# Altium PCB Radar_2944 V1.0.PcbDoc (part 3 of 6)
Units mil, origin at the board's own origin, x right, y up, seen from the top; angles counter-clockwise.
Board outline 3544.83 x 2556.65 mil, 8 copper layers (Top Layer, GND1, SIG1, PWR1, PWR2, SIG2, GND2, Bottom Layer), stack 55.2 mil thick; 301 components, 253 nets, 1055 pads, 1340 vias.
Unrouted connection lines stored in the file: 12.
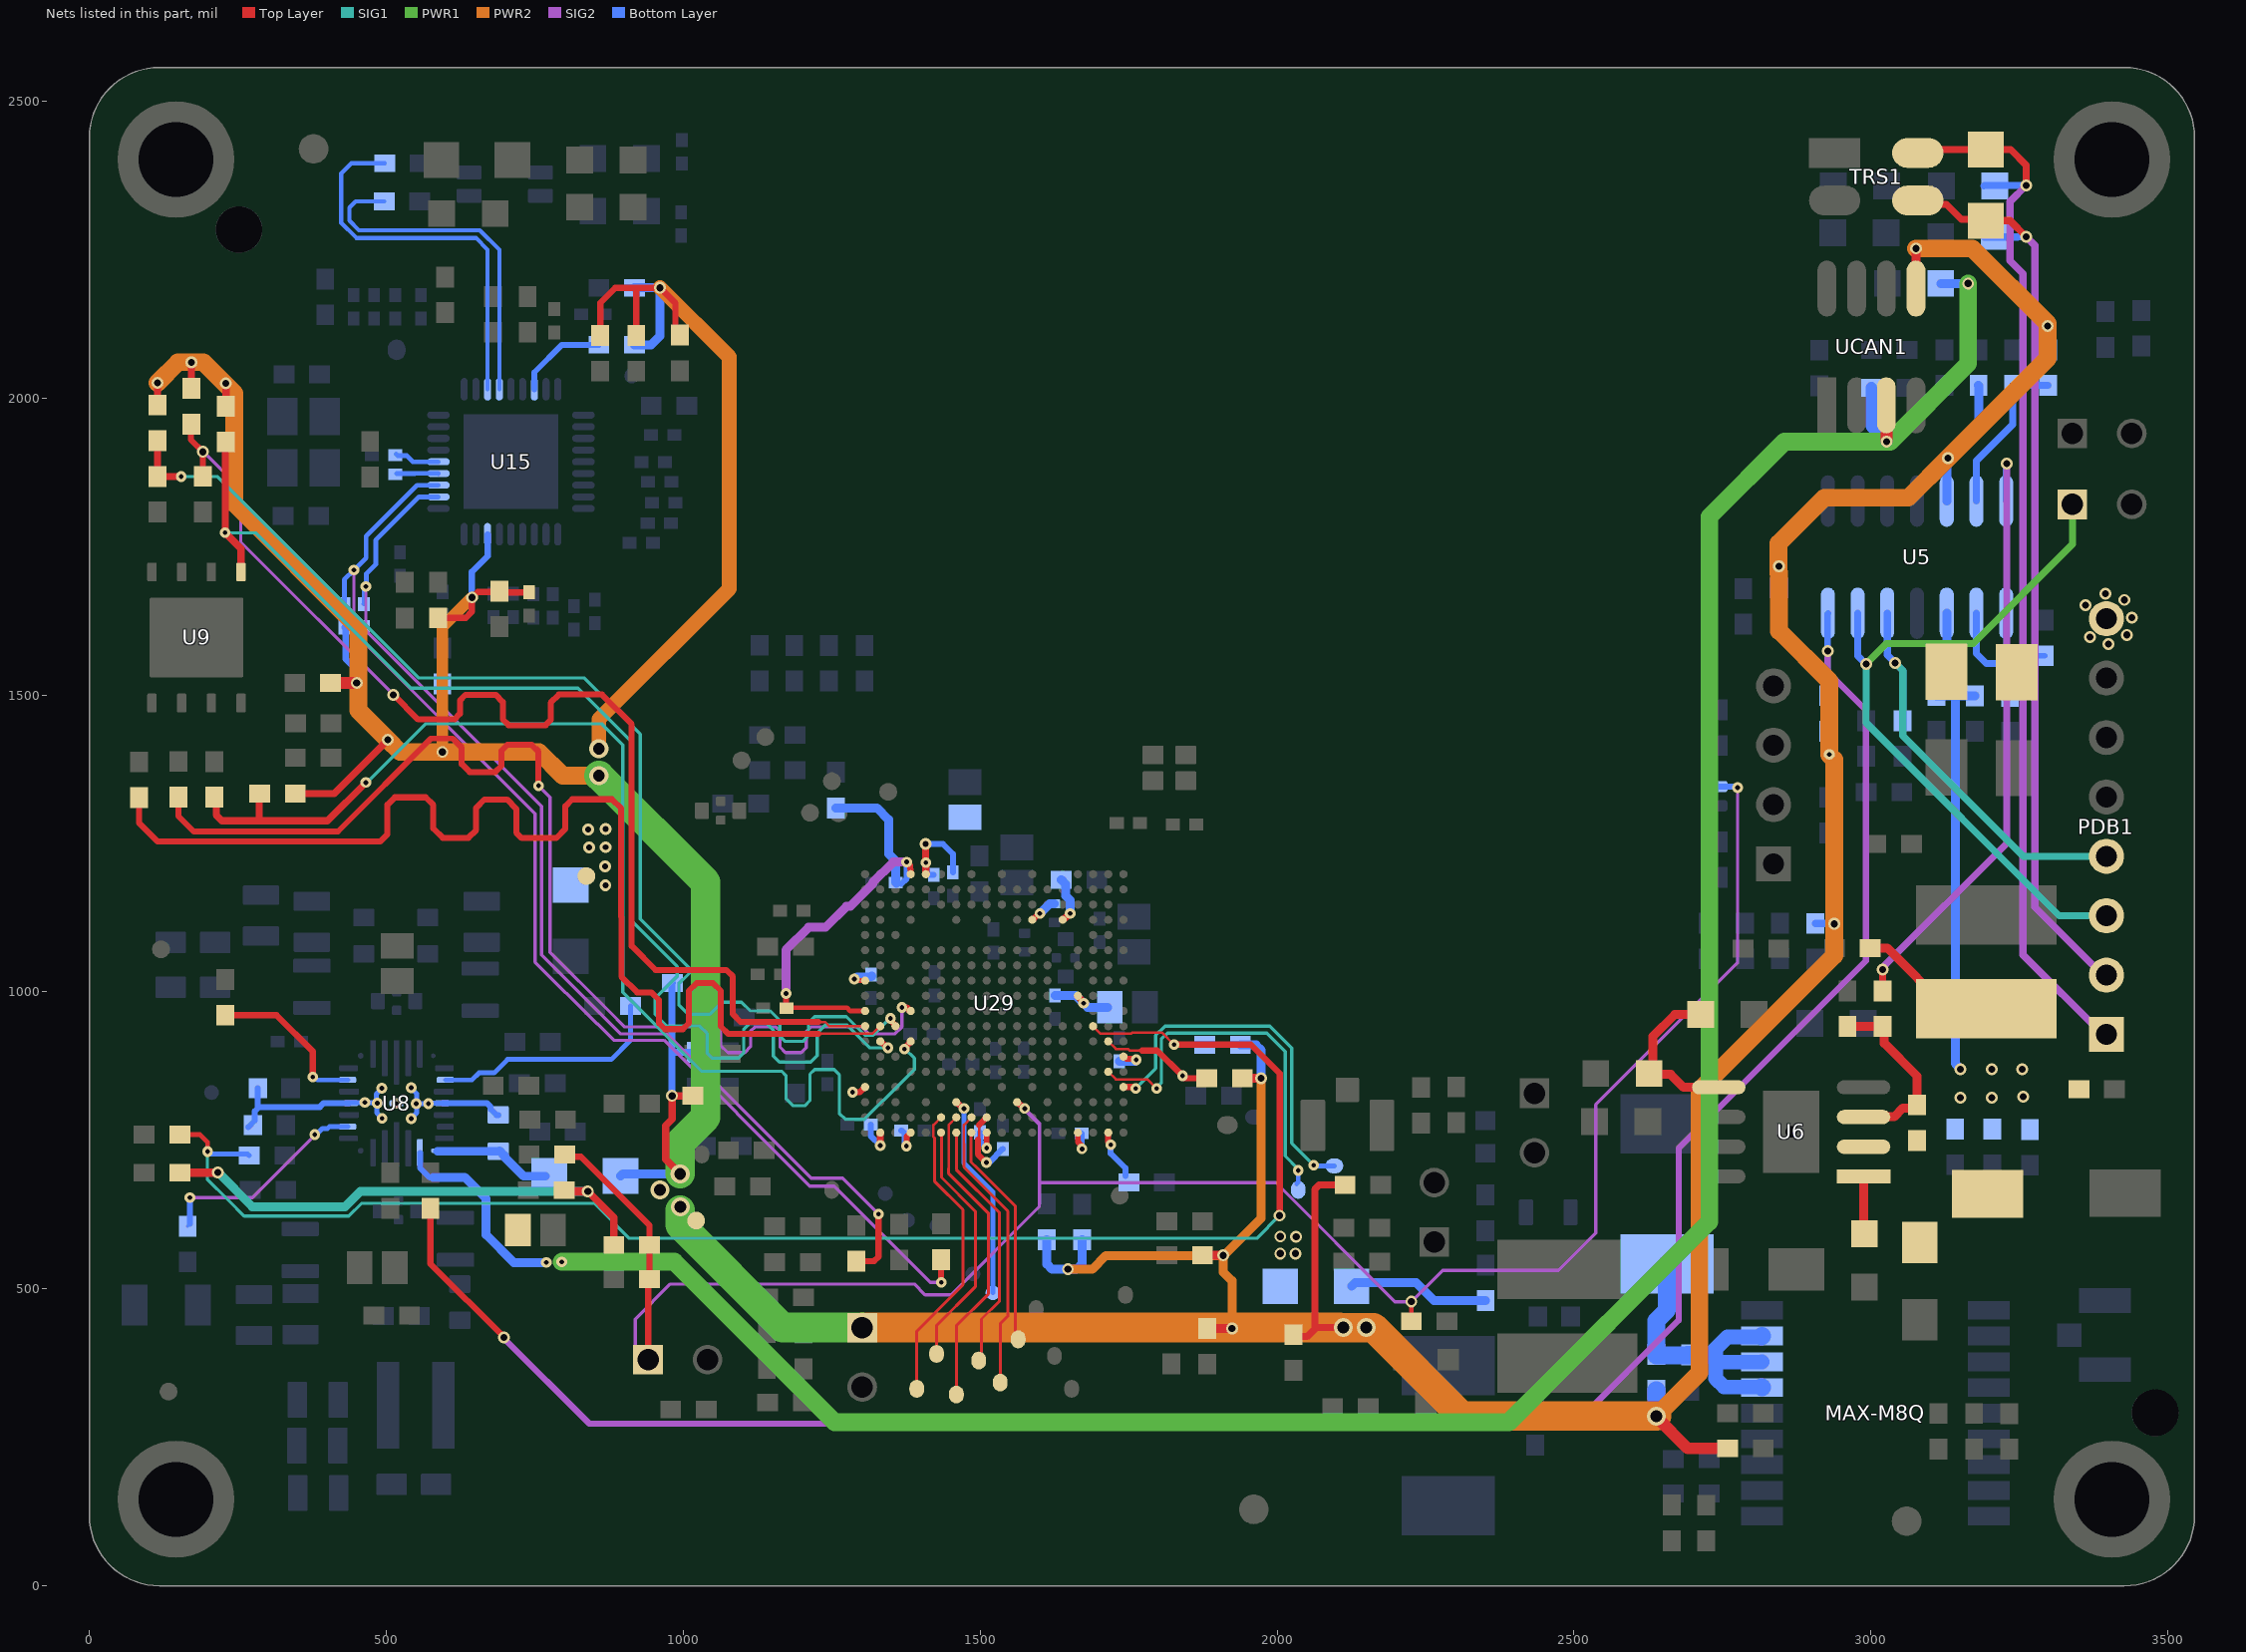
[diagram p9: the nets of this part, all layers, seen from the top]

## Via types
v1: diameter 13.77, hole 5.9, Top Layer to GND1, tented both sides, 427 vias
v2: diameter 18, hole 8, Top Layer to Bottom Layer, tented both sides, 341 vias
v3: diameter 13.77/13.77 (per signal layer), hole 5.9, Top Layer to GND1, tented both sides, 229 vias
v4: diameter 20, hole 12, Top Layer to Bottom Layer, tented both sides, 165 vias
v5: diameter 13.77, hole 5.9, Top Layer to GND1, tented top, 140 vias
v6: diameter 20, hole 10, Top Layer to Bottom Layer, tented both sides, 19 vias
v7: diameter 32, hole 20, Top Layer to Bottom Layer, tented both sides, 9 vias
v8: diameter 28, hole 16, Top Layer to Bottom Layer, tented both sides, 9 vias
v9: diameter 19.68, hole 7.87, Top Layer to Bottom Layer, tented both sides, 1 vias

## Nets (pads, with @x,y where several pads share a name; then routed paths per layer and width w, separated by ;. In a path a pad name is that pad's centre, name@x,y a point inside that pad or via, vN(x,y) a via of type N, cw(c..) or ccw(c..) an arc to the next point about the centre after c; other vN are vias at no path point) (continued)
1V4_SYNTH: C102.1 U29.G4 | length 47.8
  Top Layer w10.6: U29.G4@1587.71,1121.4 1592.73,1125.58 v2(1600.51,1132.05)
  Bottom Layer w15: v2(1600.51,1132.05) 1616.76,1148.31 C102.1@1624.94,1148.31
1V8: C5.2 C107.2 C110.1 C111.2 C112.1 C113.2 C163.2 C164.2 C165.2 C168.2 C170.2 C172.2 pad.39@836.84,1195.02 R104.2 R156.2 U29.D9 U29.D18 U29.E4 U29.K17 U29.K18 U29.P1 U29.R1 U29.U18 U29.V10 | length 1432.4
  Top Layer w4.19: 1496.12,751.72 1498.15,753.74 1498.15,768.45 ; 1498.13,768.46 1498.13,775.91
  Top Layer w8: C163.2@1173.56,973.26 1275.85,973.26 1281.25,967.86 U29.V10@1306.22,967.86
  Top Layer w10: v2(1172.94,997.35) 1172.94,977.83 C163.2@1175.42,975.34 ; v2(1376.35,1218.68) 1382.26,1212.77 1382.26,1206.87 1382.99,1206.14 U29.R1@1382.99,1198.17 ; 1496.12,751.7 1496.12,726.91 v2(1510.35,712.68) ; 1498.13,775.91 U29.K17@1510.94,788.72 ; v2(1510.94,737.09) U29.K18@1510.94,763.13 ; U29.D18@1664.49,763.13 1664.49,747.34 1669.92,741.91 1669.92,737.21 v2(1671.45,735.68)
  Top Layer w12: v2(1331.81,741.22) U29.U18@1331.81,763.13 ; v6(1408.35,1249.18) v2(1408.35,1217.68) 1408.35,1216.68 1408.58,1216.45 U29.P1@1408.58,1198.17 ; U29.E4@1638.9,1121.4 1643.92,1125.58 v2(1651.69,1132.05) ; U29.D9@1664.49,993.45 1668.48,988.3 1674.15,980.99 v2@1675.01,979.88
  SIG2 w15: v2(1172.94,997.35) 1172.94,1070.46 1211.09,1108.61 1239.42,1108.61 1274.84,1144.03 1281.06,1144.03 1318.9,1181.86 1318.9,1183.8 1353.78,1218.68 v2(1376.35,1218.68)
  Bottom Layer w10: C172.2@1316.07,776.47 1316.07,756.96 v2(1331.81,741.22) ; C5.2@1367.02,1181.56 1376.35,1190.89 v2(1376.35,1218.68) ; v2(1408.35,1217.68) 1408.35,1202.44 1414.04,1196.75 C113.2@1421.85,1196.75 ; v6(1408.35,1249.18) 1437.13,1249.18 1454.02,1232.29 C107.2@1454.02,1201.22 ; C165.2@1499.75,763.55 1499.75,748.28 v2(1510.94,737.09) ; v2(1510.35,712.68) 1515.05,712.68 C164.2@1538.03,735.65 ; v2@1670.96,736.07 C170.2@1670.96,761.82
  Bottom Layer w15: R156.2@1256.95,1309.67 1326.05,1309.67 1345.7,1290.02 1345.7,1232.37 1358.01,1220.06 C5.2@1358.01,1184.12 C5.2@1359.03,1183.1 ; C168.2@1626.1,993.77 1661.11,993.77 v2(1674.01,980.88) 1680.92,973.96 C110.1@1714.78,973.96 ; C111.2@1636.51,1188.85 1643.89,1181.47 1643.89,1161.91 1651.64,1154.17 v2@1651.64,1132.05
  other v6: 868.92,1179.67 868.57,1211.11 841.35,1243.07 868.97,1243.64 840.21,1273.54 869.12,1274.13
3.0V_GPS: CBG1.1 CGP2.2 MAX-M8Q.6 MAX-M8Q.7 MAX-M8Q.8 RG9.1 | length 567
  Bottom Layer w25: 2729.08,389 2730.46,390.39 2738.57,390.39 2740.57,376.71 2815.79,376.71 MAX-M8Q.7@2816.39,377.31 ; 2733.63,394.66 2758.05,419.08 2814.85,419.08 MAX-M8Q.8@2815.64,419.87 ; 2738.17,380.97 2738.17,349.39 2752.81,334.75 MAX-M8Q.6@2815.64,334.75
  Bottom Layer w30: CBG1.1@2656.45,541.76 CBG1.1@2656.45,541.76 2656.4,464.33 2638.45,446.38 2638.45,387.91 2695.45,387.91 CGP2.2@2695.45,388.76 ; CGP2.2@2690.84,389 2729.08,389 ; MAX-M8Q.6@2815.64,334.75 MAX-M8Q.6@2816.39,334 ; MAX-M8Q.8@2815.64,419.87 MAX-M8Q.8@2816.39,420.61
3V3: C174.2 C175.2 C176.2 C177.2 R11.1 U29.A13 U29.B18 U29.R18 U29.V8 U29.V15 | length 268.7
  Top Layer w8: v2(1288.17,1021.54) 1290.67,1019.04 U29.V8@1306.22,1019.04
  Top Layer w10: v2(1285.35,831.31) 1297.62,831.31 U29.V15@1306.22,839.9 ; v2(1375.85,740.68) 1375.85,755.99 U29.R18@1382.99,763.13 ; U29.B18@1715.67,763.13 1715.67,746.86 v2(1719.85,742.68) ; U29.A13@1741.26,891.09 1742.28,891.09 1746.2,887.16 1761.24,887.16 v2(1762.74,885.66)
  Bottom Layer w10: C177.2@1367.15,766.55 1367.99,766.55 1372.83,761.7 1372.83,745.86 1375.85,742.84 v2(1375.85,740.68) ; v2(1719.85,742.68) 1719.85,727.94 1744.57,703.22 C175.2@1744.57,689.93
  Bottom Layer w15: v2(1288.17,1021.54) 1288.98,1021.54 1292.88,1025.44 1316.61,1025.44 C174.2@1317.65,1026.48 ; C176.2@1734.35,883.25 1760.32,883.25 v2(1762.74,885.66)
  other v4: 2005.24,559.56 2031,559.56 2005.24,588.1 2032.03,587.84
3V3_VIO: C12.2 C32.1 C35.1 pad.39@1021.65,614.87 PSO1.1 R1.2 R4.1 R11.2 R18.1 R34.1 R37.1 R40.2 R43.2 R44.2 R45.2 R53.1 R106.2 R116.2 R253.2 R254.2 R255.2 R256.2 R257.2 R262.2 R263.2 R264.2 R271.2 R272.2 R273.2 R276.2 R277.2 R278.2 R279.2 R280.2 R309.2 R331.2 R333.2 R409.2 RCN25.2 RG1.2 RG9.2 Rs301.2 U5.5 U15.34 UCAN1.5 | length 12660.3
  Top Layer w10.6: R1.2@587.52,1629.69 633.61,1629.69 644.12,1640.21 v4(644.12,1664.19) 645.01,1664.19 654.03,1673.22 686.02,1673.22 C32.1@690.38,1677.59 ; C32.1@690.38,1672.59 737.85,1672.59 C35.1@740.58,1675.33 ; R257.2@860.25,2105.07 860.25,2160.28 885.39,2185.42 920.95,2185.42 ; R256.2@920.95,2105.07 920.95,2185.42 ; R255.2@986.69,2105 986.69,2159.74 v4(961.01,2185.42) 920.95,2185.42
  Top Layer w12: v4(114.62,2025.41) 114.62,1988.43 R44.2@115,1988.05 ; R40.2@172,2016 v4(172,2059.56) ; R43.2@230.06,1986.06 v4@230.06,2024.04 ; R45.2@346.96,1333.84 412.23,1333.84 v4(502.8,1424.41) ; v4(839.38,663.96) 883.25,620.09 R264.2@883.25,573.99 ; v7(994.77,693.81) 970.34,718.23 970.34,775.03 981.25,785.93 v4(981.25,824.97) 1006.52,824.97 R273.2@1008.64,827.1 ; R263.2@2027.33,419.83 2050.48,419.83 2063.31,432.66 ; v7(2111.46,434.76) 2065.41,434.76 2063.31,432.66 ; R333.2@2114.45,674.76 2070.34,674.76 2063.31,667.73 2063.31,432.66
  Top Layer w15: R262.2@152.34,695.6 215.9,695.6 v4(216.42,696.12) ; R106.2@799.35,666.13 801.52,663.96 v4(839.38,663.96) ; R309.2@1874.45,556.76 v4@1909.11,556.76 ; R331.2@1882.33,433.28 v4(1923.98,433.28) ; R272.2@1941.6,854.78 v4(1973.01,854.78) ; UCAN1.5@3075.6,2176.2 v4(3075.6,2251.61) ; UCAN1.5@3075.7,2184.31 UCAN1.5@3078.86,2187.46
  Top Layer w20: R37.1@405.98,1520.33 v4(450.19,1520.33) ; v7(2638.45,285.85) 2638.45,284.14 2691.05,231.54 RG1.2@2758.54,231.54
  PWR1 w50: v7(857.96,1364.01) 858.36,1364.01 1037.48,1184.89 1037.48,788.66 994.77,745.95 v7(994.77,693.81) ; v7@994.77,632.49 994.77,607.78 1167.46,435.09 1301.11,435.09 PSO1.1@1301.45,434.76
  PWR2 w15: v4(1647.67,532.95) 1688.66,532.95 1711.87,556.17 v4@1909.11,556.17 ; v4(1909.11,556.36) v4@1909.11,556.17 ; v4(1923.98,433.28) 1923.98,434.84 1923.98,513.6 1909.11,528.47 v4@1909.11,556.17 ; v4(1973.01,854.78) 1973.01,618.86 1913.02,558.86 1912.96,558.86 1910.27,556.17 v4@1909.11,556.17
  PWR2 w20: v4(594.45,1404.01) 594.45,1614.51 v4(644.12,1664.19)
  PWR2 w25: v7(857.96,1409.13) 857.96,1459.31 1077.29,1678.65 1077.29,2069.13 v4(961.01,2185.42)
  PWR2 w30: v4(114.62,2025.41) 149.43,2060.22 171,2060.22 191.88,2060.22 227.11,2024.98 244.29,2007.81 244.29,1821.89 453.23,1612.95 453.23,1520.33 453.23,1473.85 502.74,1424.34 523.05,1404.03 v4(594.45,1404.01) 757.16,1404.03 797.19,1364.01 v7(857.96,1364.01) ; v7(2638.45,285.85) 2711.06,358.46 2711.06,834.35 2937.86,1061.15 v4(2937.86,1114.48) 2937.86,1391.37 v2(2929.65,1399.57) ; 2844.13,1705.29 2844.13,1754.94 2921.26,1832.07 3062.85,1832.07 v4(3129.28,1898.49) 3297.24,2066.46 v4(3297.24,2120.85) 3297.24,2125.2 3170.83,2251.61 v4(3075.6,2251.61) ; 2845.27,1706.44 2845.27,1607.79 2929.65,1523.41 v2@2929.65,1402.27
  PWR2 w50: PSO1.1@1301.45,434.76 1301.53,434.84 1923.98,434.84 2105.14,434.84 2105.22,434.76 v7(2111.46,434.76) v7(2149.98,434.76) 2162.34,434.76 2311.25,285.85 v7(2638.45,285.85)
  SIG1 w15: v4(216.42,696.12) 274.27,638.27 430.41,638.27 456.09,663.96 v4(839.38,663.96)
  Bottom Layer w10.6: v4(450.19,1520.33) 450.19,1541.81 431.58,1560.43 431.58,1611.67 R4.1@429.48,1613.76 431.58,1615.86 460.11,1615.86 R34.1@462.2,1613.76 ; v4(644.12,1664.19) 644.12,1707.2 670.59,1733.66 U15.34@670.59,1770.41
  Bottom Layer w12: v4(594.45,1404.01) R280.2@594.45,1518.76 ; v4@980.8,831.42 980.8,895.83 ; R276.2@981.73,1015.17 980.8,1014.25 980.8,895.83 ; R277.2@1021.31,898.39 983.36,898.39 980.8,895.83 ; RCN25.2@2906.19,1115.14 2937.2,1115.14 v4(2937.86,1114.48)
  Bottom Layer w15: R116.2@894.45,689.94 898.31,693.81 v7(994.77,693.81) ; R254.2@917.96,2089.55 945.93,2089.55 960.56,2104.19 v4@960.56,2185.42 ; R253.2@917.96,2185.42 v4@960.56,2185.42 ; v4(961.01,2185.42) v4@960.56,2185.42 ; R278.2@1612.22,582.98 1612.22,541.74 1621.01,532.96 1662.82,532.96 1671.61,541.74 R279.2@1671.61,582.58 ; R271.2@1938.07,910.88 1964.23,910.88 1973.01,902.09 v4(1973.01,854.78) ; R11.2@2125.24,504.38 2131.7,510.85 2233.66,510.85 2264.47,480.04 R409.2@2350.98,480.04 ; Rs301.2@2845,1680 v4(2845,1716.75) ; R18.1@2928.04,1438.73 2929.65,1437.12 v2(2929.65,1399.57) ; U5.5@3127.45,1826.48 3127.45,1895.31 3129.28,1897.14 v4(3129.28,1898.49) 3129.28,1899.85 3131.78,1902.35 3131.78,1903.46 3181.46,1953.14 3181.46,2020.63 C12.2@3181.01,2021.08 ; v4(3297.24,2120.85) 3297.24,2081.95 R53.1@3298.11,2081.08
  Bottom Layer w30: v7(2638.45,285.85) RG9.2@2638.45,329.76
  other v4: 229.54,2024.56
  other v7: 995.51,637.95 960.71,666.76
3V3EN: R7.1 R8.2 R12.1 U6.3 | length 312.3
  Top Layer w15: R7.1@2960.45,941.76 R8.2@3019.45,941.76 ; U6.3@2987.58,789.38 2987.94,789.73 3039.02,789.73 3053.86,804.58 R12.1@3077.45,804.58 ; R8.2@3015.71,941.35 3022.14,934.91 3022.14,913.47 3077.45,858.17 R12.1@3077.45,809.76
3V3REG_EN: R8.1 U5.7 | length 1037.7
  Top Layer w12: R8.1@3019.45,1001.76 v4(3019.45,1037.76)
  SIG2 w12: v4(3019.45,1037.76) 3019.45,1039.93 3023.45,1043.93 3023.45,1045.07 3228.51,1250.14 v4(3228.51,1889.43)
  Bottom Layer w12: U5.7@3227.45,1826.48 3227.45,1883.17 3228.51,1884.23 v4(3228.51,1889.43)
5V0: C120.1 R16.2 RCN1.2 U8.10 UCAN1.3 | length 4594.5
  Top Layer w20: UCAN1.3@3025.7,1987.46 3026.02,1987.14 v4@3026.02,1928.39
  PWR1 w30: v2(795.58,545.31) 795.86,545.6 984.87,545.6 1255.02,275.45 2390.16,275.45 2727.93,613.23 2727.93,1800.18 2854.22,1926.47 v4(3026.39,1926.47) 3031.99,1926.47 3163.45,2057.93 v4(3163.45,2192.77)
  Bottom Layer w10: U8.10@556.9,729.17 556.9,703.57 572.78,687.69 579.47,687.69
  Bottom Layer w15: 579.47,687.69 632.16,687.69 668.11,651.74 668.11,591.1 714.75,544.46 v2@769.51,544.46 ; RCN1.2@3117.45,2192.77 v4(3163.45,2192.77)
  Bottom Layer w20: R16.2@3000.59,2017.08 3000.59,1952.27 v4(3026.39,1926.47)
  other v2: 769.51,544.63
12V_IN: C80.1 Cu1.1 Cu3.2 Cu4.1 Cu5.1 Cu7.1 L4.2 R12.2 R52.2 R332.2 TVS2.K U5.10 U6.2 | length 1082.5
  Top Layer w15: R332.2@2998.45,1073.76 3027.17,1073.76 3129.17,971.75 L4.2@3193.99,971.75
  Bottom Layer w15: U5.10@3127.45,1637.51 3127.45,1553.13 3110.04,1535.73 C80.1@3110.04,1498.73 3144.17,1498.73 ; v4(3150.42,869.67) 3150.42,871.03 3141.72,879.73 3141.72,1496.28 3144.17,1498.73 ; R52.2@3175.02,1498.57 3174.86,1498.73 3144.17,1498.73
  other v4: 3150.42,821.83 3203.14,821.83 3256.07,823.34 3203.14,869.67 3254.65,869.67
+3.3VD: C124.2 R116.1 U8.9 | length 198.1
  Bottom Layer w15: 586.11,731.73 C124.2@688.49,731.73 ; C124.2@690.75,732.43 698.71,724.47 698.71,722.57 731.61,689.67 R116.1@767.62,689.67
AGND: C3.1 C123.1 C124.1 NT1.2 NT2.1 NT3.1 NT4.1 U8.5 U8.19 | length 550
  Bottom Layer w8.3: U8.19@437.46,812.84 438.15,813.53 463.53,813.53 v2(463.73,813.74) 464.23,813.24 v2@484.23,813.24 ; v2@485.31,813.33 v2(484.73,812.74) ; v2(492.33,837.74) 492.33,837.18 483.17,828.03 483.17,814.29 v2@484.23,813.24 ; v2(492.93,786.94) 492.93,787.51 483.79,796.65 483.79,811.8 v2(484.73,812.74) ; v2(541.93,786.74) 541.93,787.14 551.24,796.45 551.24,811.03 v2@550.5,811.77 ; v2(541.93,838.54) 541.93,837.93 551.02,828.83 551.02,812.64 v2(550.33,811.94) ; v2@548.94,813.33 v2(550.33,811.94) ; U8.5@594.3,812.34 571.54,812.34 v2(570.97,811.77) v2@550.5,811.77 ; v2@484.23,813.24 v2(484.73,812.74) ; v2(550.33,811.94) v2@550.5,811.77
  Bottom Layer w10: C123.1@267.7,772.46 278.44,783.21 278.44,798.92 285.81,806.29 ; 283.7,804.18 C3.1@283.7,838.07 ; 283.7,806.29 388.12,806.29 394.67,812.84 U8.19@437.46,812.84 ; U8.5@594.3,812.34 669.92,812.34 675.78,806.48 675.78,802.52 685.54,792.76 C124.1@688.49,792.76
  other v2: 517.29,812.08
AR_NERROUT: DS2.2 R76.1 R271.1 U29.C11 | length 2694.9
  Top Layer w4.19: U29.C11@1690.08,942.27 1702.87,929.47 1746.56,929.47 1753.93,929.49 1756.22,931.77 1806,931.77 v2(1826.57,911.2)
  Top Layer w8.3: DS2.2@152.34,759.66 186.36,759.66 199.11,746.91 v2(199.11,731.09)
  Top Layer w10.6: v2(1826.57,911.2) 1955.85,911.2 2004.51,862.54 2004.51,624.08 v4(2003.85,623.43)
  SIG1 w5.5: v2(199.11,731.09) 198.67,730.65 198.67,684.59 233.94,649.32 260.74,622.52 436.93,622.52 458.37,643.96 850.44,643.96 909.23,585.16 1965.59,585.16 v4(2003.85,623.43) ; v2(1826.57,911.2) v2@1827.99,909.78
  Bottom Layer w8.3: v2(199.11,731.09) 203.39,726.81 266.82,726.81 R76.1@269.09,724.53 ; v2(1826.57,911.2) 1826.89,910.88 R271.1@1863.39,910.88
AR_NRST: C105.2 D4.2 J11.1 R99.1 R264.1 R266.1 U29.H16 | length 3475.7
  Top Layer w8: R266.1@2225.96,445.59 v4(2225.96,478.37)
  Top Layer w10.6: R99.1@800.58,726.29 804.44,722.43 827.78,722.43 943.25,606.95 R264.1@943.25,573.99 C105.2@943.25,516.71 940.82,514.27 J11.1@940.82,380.84 ; U29.H16@1562.12,814.31 1567.14,810.13 v2(1574.92,803.66)
  SIG2 w5.5: J11.1@919.16,376.14 919.16,448.96 978.26,508.06 1389.28,508.06 1407.22,490.12 1451.33,490.12 1599.46,638.25 1599.46,643 ; 1598.4,777.41 1574.92,800.9 v2(1574.92,803.66) 1599.79,778.79 1599.79,678.71 ; 1599.79,643 1599.79,678.71 ; v2(2775.15,1344.1) 2775.15,1048.9 2536.54,810.3 2536.54,593.94 2473.59,530.99 2278.58,530.99 v4(2225.96,478.37) 2198.44,478.37 1998.1,678.71 1599.79,678.71
  Bottom Layer w10: D4.2@2743.49,1345.86 2771.22,1345.86 2772.98,1344.1 v2(2775.15,1344.1)
AR_QSPI_CLK: R47.2 U29.R10 | length 1973.6
  Top Layer w10: R47.2@149.79,1327.6 149.79,1296.19 175.87,1270.11 418.65,1270.11 575.14,1426.59 611.79,1426.59 627.05,1411.32 627.05,1383.64 640.42,1370.27 683.44,1370.27 694.12,1380.95 694.12,1406.38 703.59,1415.85 745.11,1415.85 756.32,1404.64 v2(756.32,1347.09)
  Top Layer w10.6: v2@1368.19,973.79 1376.19,973.79 1382.13,967.86 U29.R10@1382.99,967.86
  SIG2 w5.5: v2(756.32,1347.09) 775.88,1327.53 775.88,1066.63 874.31,968.21 901.56,940.95 1054.9,940.95 1063.02,932.83 1063.02,909.69 1074.91,897.8 1103.63,897.8 1113.38,907.55 1113.38,933.81 1120.51,940.95 1156.06,940.95 1163.06,933.94 1163.06,906.87 1172.13,897.8 1198.4,897.8 1206.91,906.32 1206.91,932.83 1215.04,940.95 1227.35,940.95 1300.78,940.95 1312.25,929.47 1356.75,929.47 1368.19,940.91 v2@1368.19,973.97
  other v2: 1368.11,973.97
AR_QSPI_CS: R43.1 U9.1 U29.U12 | length 2181.2
  Top Layer w10.6: U29.U12@1331.81,916.68 1336.83,912.5 v2(1344.6,906.02)
  Top Layer w12: R43.1@228.98,1918.49 228.98,1773.74 v2(228.51,1773.28) 255.44,1746.35 U9.1@255.44,1706.9
  SIG1 w5.5: v2(228.51,1773.28) 229.12,1772.68 280.55,1772.68 541.78,1511.45 823.1,1511.45 912.73,1421.82 912.73,1119.95 989.95,1042.74 989.95,1026.44 952.71,989.21 952.71,962.18 972.21,942.68 1027.81,942.68 1040.16,930.33 1040.16,896.96 1048.52,888.6 1092.9,888.6 1101.63,897.33 1101.63,936.71 1111.42,946.5 1140.42,946.5 1151.63,935.3 1151.63,892.21 1162.1,881.74 1214.53,881.74 1225.39,892.6 1225.39,930.36 1239.1,944.06 1275.74,944.06 1313.78,906.02 v2(1344.6,906.02)
AR_QSPI_D0: R61.2 U29.U11 | length 2052.8
  Top Layer w4.19: 1227.35,929.47 1318.05,929.47 1330.84,942.27 U29.U11@1331.81,942.27
  Top Layer w10.2: R61.2@83.55,1327.6 83.55,1284.59 115.14,1253.01 489.82,1253.01 502.01,1265.2 502.01,1315.06 514.56,1327.6 566.33,1327.6 579.12,1314.81 579.12,1275.11 595,1259.24 638.16,1259.24 651.17,1272.25 651.17,1309.71 665.36,1323.9 703.29,1323.9 719,1308.2 719,1268.29 728.18,1259.11 786.22,1259.11 801.52,1274.4 801.52,1312.72 813.07,1324.27 880.04,1324.27 895.43,1308.87 895.43,1126.27 895.95,1125.75 895.95,1025.66 922.51,999.11 946.39,999.11 959.12,986.38 959.12,947.26 969.14,937.25 999.31,937.25 1009.44,947.38 1009.44,1001.66 1022.61,1014.82 1049.98,1014.82 1063.13,1001.67 1063.13,941.96 1075.62,929.47 1227.35,929.47
AR_QSPI_D1: R40.1 R46.1 U29.V11 | length 2042.5
  Top Layer w4.19: 1227.35,949.27 1239.07,949.27 1246.07,942.27 U29.V11@1306.22,942.27
  Top Layer w10.2: R40.1@171,1955.85 171,1929.55 v4(191.25,1909.3) 191.25,1868.1 R46.1@191.37,1867.99 ; v4(511.8,1500.15) 512.19,1500.15 553.51,1458.83 614.51,1458.83 623.92,1468.24 623.92,1490.64 633.43,1500.15 684.17,1500.15 696.13,1488.19 696.13,1458.88 705.83,1449.18 768.1,1449.18 776.73,1457.8 776.73,1486.73 790.69,1500.69 863.05,1500.69 913.15,1450.59 913.15,1077.13 953.53,1036.75 1072.68,1036.75 1083.41,1026.02 1083.41,962.62 1096.75,949.27 1227.35,949.27
  SIG2 w5.5: v4@193.06,1908.73 255.07,1846.72 255.07,1756.88 v4(511.8,1500.15)
AR_QSPI_D2: R44.1 R48.1 U29.T11 | length 2031.8
  Top Layer w10: v2@1349.48,955.74 1349.48,951.05 U29.T11@1357.4,943.13
  Top Layer w10.6: U29.T11@1357.4,942.27 U29.T11@1357.4,943.13
  Top Layer w12: R44.1@114.62,1928.43 R44.1@115,1928.05 114.8,1927.85 R48.1@114.8,1867.8 v2(154.5,1867.8)
  SIG1 w5.5: v2@156.17,1867.8 215.1,1867.8 554.15,1528.74 832.8,1528.74 927.67,1433.87 927.67,1122.88 1009.92,1040.62 1009.92,1030.86 992.55,1013.5 992.55,978.5 1008.58,962.47 1044.81,962.47 1064.97,982.64 1098.13,982.64 1112.81,967.95 1146.7,967.95 1162.68,951.98 1162.68,925.91 1171.91,916.68 1201.1,916.68 1210.9,926.48 1210.9,947.98 1221.35,958.43 1227.35,958.43 1274.67,958.43 1305.75,927.35 1319.69,927.35 v2@1347.38,955.03
  other v2: 1349.07,955.23
AR_QSPI_D3: R45.1 R49.2 U29.R12 | length 2077.6
  Top Layer w10.6: v2(1372.34,903.88) 1378.81,911.66 U29.R12@1382.99,916.68
  Top Layer w12: R49.2@213.52,1327.6 213.52,1297.55 222.96,1288.11 286.09,1288.11 ; R45.1@286.96,1333.84 286.09,1332.97 286.09,1288.11 ; v2(465.42,1352.54) 400.98,1288.11 286.09,1288.11
  SIG1 w5.5: v2@463.64,1348.66 566.4,1451.42 862.39,1451.42 898.26,1415.55 898.26,999.04 1030.91,866.39 1166.13,866.39 1172.94,859.58 1172.94,820.67 1185.28,808.33 1204.63,808.33 1213.38,817.08 1213.38,861.44 1221.32,869.38 1253.98,869.38 1262.74,860.61 1262.74,795.64 1273.21,785.17 1304.81,785.17 1367.99,848.36 1389.06,869.42 1389.06,888.25 1373.42,903.88 v2(1372.34,903.88)
AR_WRMRST: R272.1 U29.B12 | length 180.5
  Top Layer w4.19: U29.B12@1715.67,916.68 1728.46,903.88 1749.28,903.88 1751.58,901.58 1768.72,901.58 1768.97,901.83 1772.45,901.83 1772.98,901.3
  Top Layer w10.6: 1772.98,901.3 1798.14,901.3 1838.58,860.86 v2@1842.67,856.78 ; v2(1840.88,858.96) 1845.06,854.78 R272.1@1866.92,854.78 ; R272.1@1881.09,854.27 R272.1@1881.6,854.78
BOOT: C1.1 U6.1 | length 97
  Top Layer w15: U6.1@2987.58,689.38 2987.58,594.42 C1.1@2989,593
BSS_UARTA_TX: pad.6 U29.M16 | length 347.3
  Top Layer w10.6: U29.M16@1459.76,814.31 1464.78,810.13 v2(1472.56,803.66)
  Bottom Layer w8.3: v2(1472.56,803.66) 1472.56,711.98 1521.54,662.99 pad.6@1521.54,493.3
CAN1H: PDB1.3 PL1.1 U5.13 | length 1227.9
  PWR1 w12: v4(2991.56,1552.27) 3025.76,1586.47 3172.04,1586.47 3339.05,1753.49 PL1.1@3339.05,1820.83
  SIG1 w12: v4(2991.56,1552.27) 2991.56,1453.31 3316.59,1128.28 PDB1.3@3396.36,1128.28
  Bottom Layer w12: U5.13@2977.45,1637.51 2977.45,1565.91 2991.08,1552.27 v4(2991.56,1552.27)
CAN1L: PDB1.4 R24.1 U5.12 | length 747
  SIG1 w12: v4(3040.67,1553.84) 3053.49,1541.02 3053.49,1431.45 3256.66,1228.28 PDB1.4@3396.36,1228.28
  Bottom Layer w12: U5.12@3027.45,1637.51 3027.45,1567.06 3053.89,1540.62 3053.89,1457.49 R24.1@3052.99,1456.59
CAN2H: PDB1.1 RCN4.1 RCN5.1 TRS1.4 | length 1806.4
  Top Layer w12: TRS1.4@3078.86,2412.57 3084.32,2418.02 3235.29,2418.02 3261.41,2391.91 v4(3261.41,2358.02)
  SIG2 w12: v4(3261.41,2358.02) 3234,2330.62 3234,2231.02 3255.74,2209.28 3255.74,1062.46 PDB1.1@3389.45,928.76
  Bottom Layer w12: RCN5.1@3189.89,2357.04 3190.88,2358.02 v4(3261.41,2358.02)
CAN2L: PDB1.2 RCN2.1 RCN4.2 TRS1.3 | length 1580.9
  Top Layer w12: TRS1.3@3058.88,2332.57 3065.69,2325.76 3127.17,2325.76 3152.18,2300.75 3171.25,2300.75 RCN4.2@3177,2295 ; RCN4.2@3193.15,2298.02 3193.77,2298.64 3233.92,2298.64 v4(3261.41,2271.15)
  SIG2 w12: v4(3261.41,2271.15) 3275.93,2256.62 3275.93,1142.27 PDB1.2@3389.45,1028.76
  Bottom Layer w12: RCN2.1@3189.89,2271.78 3190.7,2270.97 3246.87,2270.97 3247.05,2271.15 v4(3261.41,2271.15)
CAN_EN: R53.2 R54.2 U5.6 | length 279.2
  Bottom Layer w12: U5.6@3177.45,1826.48 3177.45,1894.04 3238.73,1955.32 3238.73,2020.89 R54.2@3238.92,2021.08 R53.2@3298.11,2021.08
CAN_nFAULT: R233.2 U5.8 | length 130
  Bottom Layer w10: U5.8@3227.45,1637.51 3227.45,1577.37 3238.92,1565.91 R233.2@3292.55,1565.91
CAN_WAKE: R55.1 U5.9 | length 176.3
  Bottom Layer w12: U5.9@3177.45,1637.51 3177.45,1569.69 3194,1553.13 3215.36,1553.13 3234.35,1534.14 3234.35,1497.81 R55.1@3233.95,1497.41
CANB_NSTB: R17.1 R18.2 U5.14 | length 3796.5
  Top Layer w10.6: R17.1@574.32,635.6 574.32,542.28 v4(698.2,418.4)
  SIG2 w10.6: v4@697.86,417.02 841.9,272.98 2502.26,272.98 2676.13,446.85 2676.13,736.67 2991.56,1052.1 2991.56,1474.57 2926.96,1539.17 v4@2926.96,1567.77
  Bottom Layer w10.6: U5.14@2927.45,1637.51 2926.59,1636.65 2926.59,1500.18 R18.2@2928.04,1498.73
  other v4: 2926.96,1573.82
CSI2_RX0_0_N: pad.32 U29.N18 | length 412.5
  Top Layer w5: pad.32@1426.64,401.16 1426.64,438.43 1491.67,503.45 1491.67,630.65 1434.84,687.48 1434.84,702.68 1434.83,754.26 ccw(c1422.84,754.26) 1434.34,757.68 1434.2,758.14 U29.N18@1434.17,763.13
CSI2_RX0_0_P: pad.21@1393.26,331.76 U29.N17 | length 524.5
  Top Layer w4: 1421.38,755.72 1421.38,775.93 U29.N17@1434.17,788.72
  Top Layer w5: pad.21@1393.26,322.16 1393.26,429.3 1470.9,506.94 1470.9,633.46 1422.84,681.53 1422.84,754.26 1421.38,755.72
CSI2_RX0_1_N: pad.21@1497.54,379.3 U29.M18 | length 426.3
  Top Layer w5: U29.M18@1459.88,763.01 1459.88,700.73 1532.6,628.02 1532.6,479.61 1502.18,449.19 1502.18,394.72 1501.36,393.91 1501.36,380.93 pad.21@1502.18,380.11
CSI2_RX0_1_P: pad.33 U29.M17 | length 522.2
  Top Layer w4: 1446.97,702.68 1446.97,775.93 U29.M17@1459.76,788.72
  Top Layer w5: 1446.97,702.68 1446.97,694.04 1514.23,626.78 1514.23,491.81 1459.88,437.46 pad.33@1459.88,322.16
CSI2_RX0_CLK_N: pad.19 U29.L18 | length 381.3
  Top Layer w5: U29.L18@1485.35,763.13 1484.55,762.33 1484.55,713.85 1495.72,702.68 1558.78,639.61 1558.78,430.47 1559.13,430.13 1559.13,419.83 pad.19@1563.91,415.04
CSI2_RX0_CLK_P: pad.20 U29.L17 | length 488
  Top Layer w4: 1472.56,744.57 1472.56,775.93 U29.L17@1485.35,788.72
  Top Layer w5: 1472.56,744.57 1472.56,705.03 1546.78,630.8 1546.78,454.04 1533.63,440.89 pad.20@1533.63,342.26
DSS_UARTA_RX: pad.36 U29.B14 | length 638
  Top Layer w4.19: U29.B14@1715.67,865.5 1728.46,852.7 1749.26,852.7 ; 1749.28,852.69 1781.72,852.69 v2(1797,837.4)
  SIG1 w5.5: v2(1797,837.4) 1797,838.89 1804.99,846.88 1804.99,920.29 1815.25,930.55 1982.87,930.55 2013.54,899.88 2013.54,723.7 2035.53,701.7 v2(2035.53,699.21)
  Bottom Layer w8: pad.36@2032.88,676.77 2035.53,679.42 v2(2035.53,699.21)
DSS_UARTA_TX: pad.35 U29.A15 | length 623.3
  Top Layer w10.6: U29.A15@1741.26,839.9 1759.23,839.9 v2(1761.73,837.4)
  SIG1 w5.5: v2(1761.73,837.4) 1795.59,871.26 1795.59,926.88 1811.07,942.36 1987.76,942.36 2024.54,905.58 2024.54,745.38 v2(2061.68,708.24)
  Bottom Layer w8: v2(2061.68,708.24) 2062.79,707.13 pad.35@2096.22,707.13
ET_12V: Dr8.A Dr9.A PDB1.8
  other v4: 3399.61,1585.78 3368.46,1597.34 3430.76,1601.1 3439.05,1630.25 3361.17,1651.35 3426.74,1659.89 3394.84,1670.44
ETH2_CLKOUT: R254.1 U15.16 | length 156.3
  Bottom Layer w10: U15.16@749.33,2014.6 749.33,2043.04 795.84,2089.55 R254.1@857.96,2089.55
ETH2_INT: R22.1 R34.2 U15.2 | length 1851.7
  Top Layer w10.6: R22.1@1291.45,546.76 1321.49,546.76 1328.77,554.04 v2(1328.77,626.12)
  SIG2 w5.5: v2(465.42,1682.53) 465.42,1608.37 761.55,1312.24 761.55,1062.06 894.13,929.47 972.17,929.47 1215.26,686.38 1268.51,686.38 v2(1328.77,626.12)
  Bottom Layer w8: R34.2@462.2,1653.13 463.05,1653.99 463.05,1679.67 v2@463.5,1680.12 ; v2(465.42,1682.53) 466.63,1683.74 466.63,1704.08 482.36,1719.8 482.36,1760.7 555.11,1833.45 U15.2@587.86,1833.45
ETH2_NRST: R4.2 R23.1 U15.3 | length 2030.1
  Top Layer w10.6: v2(1434.73,510.85) 1434.1,511.48 R23.1@1434.1,549.42 R23.1@1441.52,542.01
  SIG2 w5.5: v2(445.47,1710.23) 445.47,1605.28 750.55,1300.2 750.55,1050.1 854.44,946.21 855.35,946.21 883.08,918.47 967.61,918.47 1212.99,673.09 1253.77,673.09 1416.02,510.85 v2(1434.73,510.85)
  Bottom Layer w8: R4.2@429.48,1653.13 429.48,1694.24 v2(445.47,1710.23) 465.93,1730.69 465.93,1767.33 551.74,1853.14 U15.3@587.86,1853.14
ETH2_XI: R242.1 U15.5 | length 77
  Bottom Layer w8: R242.1@516.31,1905.6 518.98,1902.93 534.2,1902.93 544.61,1892.51 U15.5@587.86,1892.51
ETH2_XO: R246.2 U15.4 | length 70.7
  Bottom Layer w8: R246.2@517.41,1872.82 548.44,1872.82 548.72,1873.1 587.58,1873.1 U15.4@587.86,1872.82
ETH_TRD_N: R265.1 U15.13 | length 592.5
  Bottom Layer w7: R265.1@496.42,2331.03 448.43,2331.03 437.82,2320.41 437.82,2298.63 453.99,2282.46 657.33,2282.46 690.27,2249.51 U15.13@690.27,2014.6
ETH_TRD_P: R270.1 U15.12 | length 663.8
  Bottom Layer w7: R270.1@497.24,2395.17 441.33,2395.17 424.07,2377.9 424.07,2294.7 449.4,2269.37 650.87,2269.37 670.59,2249.65 U15.12@670.59,2014.6
FB: R56.1 R57.2 U6.5 | length 296.7
  Top Layer w15: R57.2@2722.45,962.05 R57.2@2713.04,962.05 2669.6,962.05 2632.45,924.89 2632.45,868.76 R56.1@2626.45,862.76 2627.99,861.22 2662.66,861.22 2684.5,839.38 U6.5@2743.49,839.38
FB_B1: R14.1 U8.3 | length 396.7
  Bottom Layer w8.3: U8.3@599.71,851.71 644.12,851.71 656.14,863.72 681.61,863.72 704.2,886.31 878.83,886.31 911,918.48 R14.1@911,976.2
FB_B2: R71.1 U8.21 | length 277.2
  Top Layer w10.6: R71.1@228.67,960.87 315.24,960.87 376.11,899.99 v2(376.11,856.81)
  Bottom Layer w8.3: v2(376.11,856.81) 378.74,856.81 383.84,851.71 U8.21@435.34,851.71
FB_B3: R291.1 U8.17 | length 365.7
  SIG2 w5.5: v2(169.39,653.49) 274.47,653.49 379.59,758.61 v2(379.59,759.66)
  Bottom Layer w5.5: R291.1@165.54,605.43 R291.1@169.39,609.27
  Bottom Layer w8.3: v2(379.59,759.66) 382.21,759.66 392.56,770.01 401.39,770.01 404.35,772.97 U8.17@435.34,772.97
  Bottom Layer w10: R291.1@169.39,609.27 v2(169.39,653.49)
